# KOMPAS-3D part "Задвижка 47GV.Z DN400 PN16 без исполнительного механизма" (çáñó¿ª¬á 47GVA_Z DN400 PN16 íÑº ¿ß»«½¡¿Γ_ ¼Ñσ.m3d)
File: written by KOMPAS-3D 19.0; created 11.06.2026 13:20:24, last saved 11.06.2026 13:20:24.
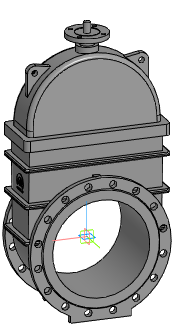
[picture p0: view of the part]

Document properties: Автор: Евгений; Полное имя файла: Z:\3.Личные\kachalov\001_3d для проектировщиков\2.2 Тип 47GVA, 47GVA.Z\_stp\_stp_Задвижка 47GVA.Z DN350-DN1200 без исп.мех\Задвижка 47GVA_Z DN400 PN16 без исполнит_ мех.m3d

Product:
- Part/product: Задвижка 47GV.Z DN400 PN16 без исполнительного механизма

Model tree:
1. Операция без истории:1  (labels: Задвижка 47GV.Z DN400 PN16 без исполнительного механизма)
